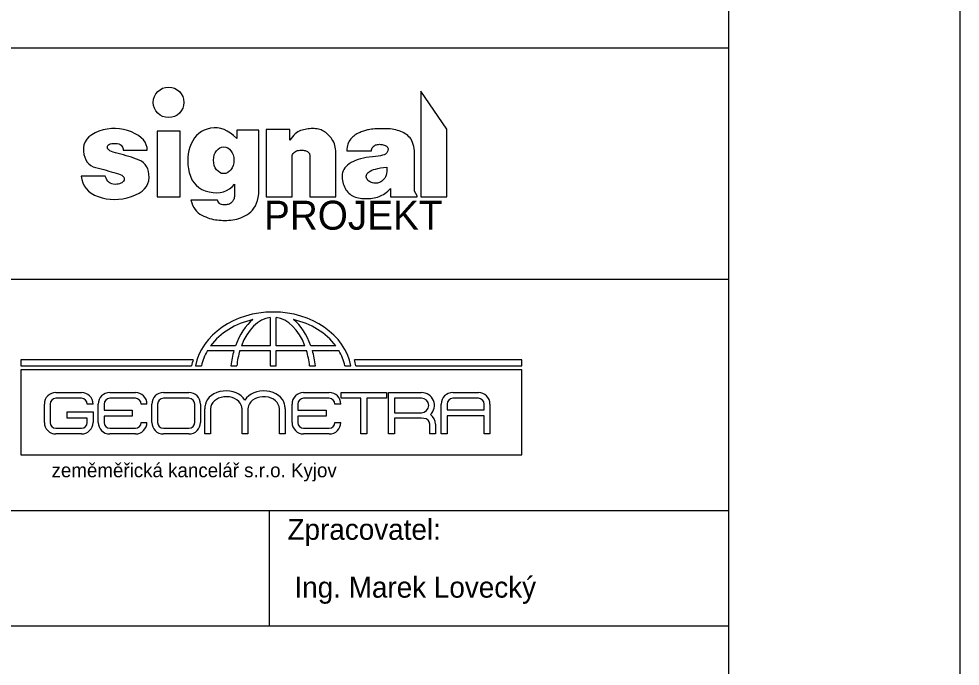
# Model space of a CAD drawing. Extents: x 1983 to 3683, y -6209 to -5764.
# Drawn here: x 2856.3 to 2937.6, y -6109.7 to -6053.7 of the extents above; entities that cross this region are included whole.
import ezdxf

# ---------------------------------------------------------------- set-up
doc = ezdxf.new("R2010")
doc.units = 0
for name, color, linetype in [('Default', 7, 'Continuous'), ('Komunikace', 7, 'Continuous'), ('Svazek obcí-chráničky', 7, 'Continuous'), ('Vrstva 19', 7, 'Continuous'), ('Vrstva 51', 7, 'Continuous')]:
    doc.layers.add(name, color=color, linetype=linetype)

msp = doc.modelspace()

# ---------------------------------------------------------------- linework, layer by layer
at = {"layer": 'Default'}
msp.add_lwpolyline([(2727.602, -6208.226), (2937.602, -6208.226), (2937.602, -5911.226), (2727.602, -5911.226)], close=True, dxfattribs=at)
at = {"layer": 'Komunikace'}
for points in [[(2893.266, -6069.106), (2893.266, -6063.266), (2891.026, -6059.986), (2891.026, -6069.106), (2893.266, -6069.106)], [(2864.538, -6069.341), (2864.9, -6069.324), (2865.266, -6069.276), (2865.637, -6069.197), (2866.013, -6069.087), (2866.368, -6068.951), (2866.676, -6068.795), (2866.937, -6068.619), (2867.151, -6068.423), (2867.318, -6068.207), (2867.439, -6067.971), (2867.512, -6067.715), (2867.539, -6067.439), (2867.528, -6067.165), (2867.49, -6066.917), (2867.424, -6066.693), (2867.33, -6066.493), (2867.209, -6066.318), (2867.059, -6066.168), (2866.882, -6066.043), (2866.678, -6065.942), (2866.458, -6065.856), (2866.236, -6065.774), (2866.012, -6065.697), (2865.786, -6065.624), (2865.557, -6065.555), (2865.326, -6065.491), (2865.092, -6065.432), (2864.857, -6065.376), (2864.635, -6065.321), (2864.444, -6065.262), (2864.283, -6065.199), (2864.153, -6065.132), (2864.053, -6065.061), (2863.983, -6064.986), (2863.944, -6064.907), (2863.936, -6064.824), (2863.952, -6064.744), (2863.989, -6064.675), (2864.045, -6064.617), (2864.121, -6064.57), (2864.217, -6064.534), (2864.332, -6064.508), (2864.468, -6064.494), (2864.623, -6064.49), (2864.778, -6064.501), (2864.914, -6064.53), (2865.029, -6064.577), (2865.123, -6064.643), (2865.198, -6064.727), (2865.253, -6064.829), (2865.287, -6064.949), (2865.302, -6065.088), (2867.381, -6065.088), (2867.361, -6064.846), (2867.299, -6064.616), (2867.194, -6064.399), (2867.046, -6064.195), (2866.856, -6064.004), (2866.622, -6063.825), (2866.345, -6063.659), (2866.026, -6063.505), (2865.684, -6063.376), (2865.339, -6063.281), (2864.991, -6063.222), (2864.641, -6063.197), (2864.288, -6063.207), (2863.932, -6063.251), (2863.574, -6063.331), (2863.213, -6063.446), (2862.875, -6063.588), (2862.586, -6063.751), (2862.345, -6063.934), (2862.153, -6064.138), (2862.009, -6064.362), (2861.915, -6064.607), (2861.868, -6064.873), (2861.871, -6065.159), (2861.91, -6065.44), (2861.976, -6065.692), (2862.069, -6065.914), (2862.187, -6066.107), (2862.332, -6066.271), (2862.503, -6066.404), (2862.7, -6066.509), (2862.923, -6066.584), (2863.158, -6066.643), (2863.389, -6066.703), (2863.617, -6066.762), (2863.841, -6066.821), (2864.061, -6066.88), (2864.278, -6066.938), (2864.491, -6066.996), (2864.701, -6067.054), (2864.893, -6067.114), (2865.054, -6067.178), (2865.185, -6067.247), (2865.284, -6067.321), (2865.353, -6067.399), (2865.391, -6067.481), (2865.398, -6067.568), (2865.374, -6067.659), (2865.327, -6067.747), (2865.266, -6067.824), (2865.191, -6067.888), (2865.101, -6067.941), (2864.997, -6067.983), (2864.878, -6068.013), (2864.745, -6068.031), (2864.598, -6068.038), (2864.45, -6068.027), (2864.314, -6067.994), (2864.19, -6067.939), (2864.079, -6067.86), (2863.98, -6067.759), (2863.894, -6067.635), (2863.82, -6067.489), (2863.758, -6067.32), (2861.678, -6067.32), (2861.722, -6067.627), (2861.805, -6067.909), (2861.928, -6068.167), (2862.091, -6068.401), (2862.293, -6068.61), (2862.535, -6068.795), (2862.816, -6068.956), (2863.137, -6069.093), (2863.48, -6069.202), (2863.828, -6069.279), (2864.181, -6069.326), (2864.538, -6069.341)], [(2870.226, -6069.106), (2870.226, -6063.426), (2868.226, -6063.426), (2868.226, -6069.106), (2870.226, -6069.106)], [(2874.086, -6071.148), (2874.254, -6071.144), (2874.424, -6071.136), (2874.596, -6071.122), (2874.77, -6071.104), (2874.944, -6071.077), (2875.118, -6071.038), (2875.292, -6070.987), (2875.465, -6070.924), (2875.638, -6070.848), (2875.811, -6070.76), (2875.984, -6070.661), (2876.156, -6070.549), (2876.32, -6070.419), (2876.469, -6070.266), (2876.601, -6070.091), (2876.718, -6069.892), (2876.819, -6069.67), (2876.904, -6069.425), (2876.973, -6069.157), (2877.026, -6068.866), (2877.026, -6063.346), (2875.106, -6063.346), (2875.106, -6064.066), (2874.84, -6063.811), (2874.57, -6063.598), (2874.295, -6063.426), (2874.016, -6063.295), (2873.733, -6063.205), (2873.446, -6063.156), (2873.154, -6063.149), (2872.858, -6063.182), (2872.571, -6063.25), (2872.306, -6063.347), (2872.062, -6063.472), (2871.84, -6063.626), (2871.64, -6063.809), (2871.462, -6064.02), (2871.306, -6064.259), (2871.171, -6064.527), (2871.06, -6064.813), (2870.975, -6065.106), (2870.916, -6065.406), (2870.883, -6065.713), (2870.876, -6066.028), (2870.895, -6066.35), (2870.94, -6066.678), (2871.011, -6067.015), (2871.111, -6067.338), (2871.243, -6067.629), (2871.409, -6067.887), (2871.607, -6068.112), (2871.838, -6068.305), (2872.101, -6068.465), (2872.397, -6068.592), (2872.726, -6068.687), (2873.062, -6068.745), (2873.381, -6068.762), (2873.681, -6068.739), (2873.964, -6068.675), (2874.229, -6068.57), (2874.477, -6068.425), (2874.707, -6068.238), (2874.918, -6068.012), (2874.918, -6069.088), (2874.9, -6069.176), (2874.877, -6069.257), (2874.849, -6069.333), (2874.817, -6069.404), (2874.781, -6069.468), (2874.74, -6069.527), (2874.694, -6069.58), (2874.644, -6069.627), (2874.588, -6069.669), (2874.526, -6069.705), (2874.456, -6069.736), (2874.379, -6069.762), (2874.295, -6069.782), (2874.204, -6069.796), (2874.106, -6069.806), (2874.001, -6069.81), (2873.897, -6069.804), (2873.804, -6069.786), (2873.72, -6069.754), (2873.647, -6069.709), (2873.584, -6069.651), (2873.532, -6069.579), (2873.489, -6069.494), (2873.457, -6069.396), (2871.15, -6069.396), (2871.219, -6069.624), (2871.302, -6069.832), (2871.399, -6070.023), (2871.51, -6070.194), (2871.635, -6070.347), (2871.773, -6070.481), (2871.926, -6070.596), (2872.092, -6070.692), (2872.264, -6070.775), (2872.435, -6070.849), (2872.604, -6070.915), (2872.772, -6070.972), (2872.938, -6071.02), (2873.103, -6071.06), (2873.266, -6071.091), (2873.428, -6071.114), (2873.59, -6071.13), (2873.753, -6071.141), (2873.919, -6071.147), (2874.086, -6071.148)], [(2883.666, -6069.106), (2883.666, -6065.306), (2883.663, -6065.136), (2883.649, -6064.973), (2883.624, -6064.816), (2883.589, -6064.666), (2883.543, -6064.522), (2883.486, -6064.385), (2883.418, -6064.255), (2883.339, -6064.131), (2883.254, -6064.015), (2883.167, -6063.907), (2883.078, -6063.807), (2882.987, -6063.716), (2882.894, -6063.632), (2882.799, -6063.557), (2882.702, -6063.49), (2882.603, -6063.431), (2882.501, -6063.38), (2882.395, -6063.335), (2882.284, -6063.298), (2882.169, -6063.268), (2882.049, -6063.244), (2881.926, -6063.227), (2881.798, -6063.218), (2881.666, -6063.215), (2881.532, -6063.218), (2881.399, -6063.226), (2881.268, -6063.239), (2881.138, -6063.257), (2881.009, -6063.28), (2880.881, -6063.308), (2880.754, -6063.341), (2880.629, -6063.378), (2880.505, -6063.427), (2880.384, -6063.492), (2880.265, -6063.573), (2880.149, -6063.671), (2880.034, -6063.785), (2879.923, -6063.915), (2879.813, -6064.062), (2879.706, -6064.226), (2879.706, -6063.306), (2877.666, -6063.306), (2877.666, -6069.106), (2879.906, -6069.106), (2879.906, -6065.546), (2879.941, -6065.455), (2879.985, -6065.374), (2880.039, -6065.303), (2880.104, -6065.242), (2880.178, -6065.191), (2880.262, -6065.15), (2880.356, -6065.119), (2880.46, -6065.098), (2880.566, -6065.085), (2880.666, -6065.078), (2880.762, -6065.077), (2880.852, -6065.082), (2880.937, -6065.094), (2881.017, -6065.111), (2881.091, -6065.135), (2881.16, -6065.165), (2881.223, -6065.199), (2881.277, -6065.238), (2881.322, -6065.28), (2881.36, -6065.326), (2881.389, -6065.375), (2881.41, -6065.428), (2881.422, -6065.485), (2881.426, -6065.546), (2881.426, -6069.106), (2883.666, -6069.106)], [(2886.229, -6069.27), (2886.391, -6069.267), (2886.548, -6069.258), (2886.702, -6069.244), (2886.851, -6069.224), (2886.995, -6069.198), (2887.135, -6069.166), (2887.271, -6069.129), (2887.403, -6069.086), (2887.532, -6069.035), (2887.659, -6068.973), (2887.784, -6068.901), (2887.908, -6068.819), (2888.03, -6068.726), (2888.15, -6068.623), (2888.269, -6068.51), (2888.386, -6068.386), (2888.386, -6069.106), (2890.706, -6069.106), (2890.706, -6069.026), (2890.466, -6068.626), (2890.466, -6065.146), (2890.44, -6064.941), (2890.404, -6064.751), (2890.359, -6064.575), (2890.304, -6064.414), (2890.239, -6064.267), (2890.165, -6064.135), (2890.082, -6064.017), (2889.989, -6063.914), (2889.888, -6063.821), (2889.78, -6063.735), (2889.667, -6063.656), (2889.547, -6063.585), (2889.421, -6063.52), (2889.288, -6063.461), (2889.15, -6063.41), (2889.005, -6063.366), (2888.853, -6063.328), (2888.694, -6063.296), (2888.527, -6063.27), (2888.354, -6063.249), (2888.173, -6063.234), (2887.985, -6063.225), (2887.79, -6063.221), (2887.588, -6063.223), (2887.389, -6063.229), (2887.205, -6063.237), (2887.036, -6063.248), (2886.881, -6063.261), (2886.741, -6063.276), (2886.616, -6063.293), (2886.506, -6063.312), (2886.41, -6063.334), (2886.322, -6063.358), (2886.232, -6063.383), (2886.142, -6063.411), (2886.051, -6063.44), (2885.96, -6063.472), (2885.868, -6063.505), (2885.775, -6063.541), (2885.682, -6063.578), (2885.589, -6063.62), (2885.496, -6063.668), (2885.405, -6063.724), (2885.315, -6063.786), (2885.226, -6063.855), (2885.138, -6063.931), (2885.05, -6064.013), (2884.964, -6064.103), (2884.884, -6064.2), (2884.815, -6064.307), (2884.756, -6064.424), (2884.709, -6064.549), (2884.672, -6064.684), (2884.646, -6064.829), (2884.631, -6064.983), (2884.626, -6065.146), (2886.746, -6065.146), (2886.762, -6065.049), (2886.786, -6064.962), (2886.819, -6064.884), (2886.86, -6064.815), (2886.91, -6064.756), (2886.969, -6064.705), (2887.036, -6064.664), (2887.112, -6064.631), (2887.193, -6064.607), (2887.274, -6064.589), (2887.355, -6064.578), (2887.437, -6064.573), (2887.52, -6064.575), (2887.603, -6064.583), (2887.687, -6064.598), (2887.771, -6064.619), (2887.851, -6064.645), (2887.923, -6064.672), (2887.985, -6064.702), (2888.039, -6064.734), (2888.084, -6064.769), (2888.121, -6064.805), (2888.148, -6064.843), (2888.167, -6064.884), (2888.178, -6064.927), (2888.183, -6064.973), (2888.182, -6065.021), (2888.175, -6065.073), (2888.161, -6065.127), (2888.141, -6065.184), (2888.115, -6065.243), (2888.082, -6065.306), (2888.032, -6065.367), (2887.951, -6065.423), (2887.839, -6065.474), (2887.698, -6065.519), (2887.526, -6065.559), (2887.323, -6065.594), (2887.091, -6065.624), (2886.828, -6065.648), (2886.556, -6065.674), (2886.296, -6065.712), (2886.049, -6065.76), (2885.814, -6065.818), (2885.591, -6065.887), (2885.381, -6065.967), (2885.183, -6066.057), (2884.997, -6066.157), (2884.828, -6066.265), (2884.679, -6066.378), (2884.552, -6066.495), (2884.445, -6066.617), (2884.36, -6066.743), (2884.295, -6066.874), (2884.251, -6067.009), (2884.228, -6067.149), (2884.22, -6067.29), (2884.221, -6067.43), (2884.231, -6067.569), (2884.25, -6067.707), (2884.278, -6067.844), (2884.315, -6067.979), (2884.361, -6068.114), (2884.416, -6068.247), (2884.479, -6068.375), (2884.549, -6068.494), (2884.626, -6068.605), (2884.709, -6068.706), (2884.8, -6068.799), (2884.898, -6068.883), (2885.002, -6068.957), (2885.114, -6069.023), (2885.232, -6069.081), (2885.356, -6069.131), (2885.486, -6069.174), (2885.622, -6069.208), (2885.765, -6069.235), (2885.913, -6069.254), (2886.068, -6069.266), (2886.229, -6069.27)], [(2886.945, -6067.925), (2886.842, -6067.905), (2886.747, -6067.877), (2886.66, -6067.841), (2886.581, -6067.797), (2886.511, -6067.746), (2886.448, -6067.687), (2886.393, -6067.62), (2886.346, -6067.545), (2886.312, -6067.468), (2886.294, -6067.391), (2886.293, -6067.315), (2886.308, -6067.24), (2886.341, -6067.165), (2886.39, -6067.092), (2886.456, -6067.02), (2886.538, -6066.948), (2886.642, -6066.88), (2886.77, -6066.817), (2886.924, -6066.759), (2887.103, -6066.707), (2887.307, -6066.66), (2887.537, -6066.618), (2887.791, -6066.581), (2888.071, -6066.55), (2888.075, -6066.748), (2888.067, -6066.931), (2888.045, -6067.097), (2888.01, -6067.246), (2887.963, -6067.38), (2887.902, -6067.497), (2887.829, -6067.599), (2887.743, -6067.684), (2887.649, -6067.755), (2887.554, -6067.814), (2887.457, -6067.862), (2887.358, -6067.898), (2887.257, -6067.923), (2887.155, -6067.935), (2887.051, -6067.936), (2886.945, -6067.925)]]:
    msp.add_lwpolyline(points, dxfattribs=at)
msp.add_circle((2869.226, -6060.946), 1.32, dxfattribs=at)
msp.add_ellipse((2873.986, -6065.946), major_axis=(0, 1.16), ratio=0.758621, dxfattribs=at)
at = {"layer": 'Svazek obcí-chráničky'}
for p, q in [((2877.997, -6079.539), (2877.997, -6081.985)), ((2878.504, -6081.985), (2878.504, -6079.537)), ((2875.003, -6081.985), (2872.858, -6081.985)), ((2877.997, -6081.985), (2875.52, -6081.985)), ((2880.998, -6081.985), (2878.504, -6081.985)), ((2883.66, -6081.985), (2881.515, -6081.985)), ((2872.583, -6082.397), (2874.871, -6082.397)), ((2875.381, -6082.397), (2877.997, -6082.397)), ((2877.997, -6082.397), (2877.997, -6083.717)), ((2878.504, -6083.717), (2878.504, -6082.397)), ((2878.504, -6082.397), (2881.138, -6082.397)), ((2881.648, -6082.397), (2883.935, -6082.397)), ((2871.352, -6083.186), (2856.472, -6083.186)), ((2856.472, -6083.186), (2856.472, -6083.717)), ((2856.472, -6083.717), (2871.215, -6083.717)), ((2871.54, -6083.717), (2872.057, -6083.717)), ((2874.614, -6083.717), (2875.114, -6083.717)), ((2877.997, -6083.717), (2878.504, -6083.717)), ((2881.405, -6083.717), (2881.905, -6083.717)), ((2884.461, -6083.717), (2884.978, -6083.717)), ((2899.75, -6083.186), (2885.272, -6083.186)), ((2885.41, -6083.717), (2899.75, -6083.717)), ((2899.75, -6083.717), (2899.75, -6083.186)), ((2899.749, -6084.061), (2856.466, -6084.061)), ((2856.466, -6084.061), (2856.466, -6091.399)), ((2899.749, -6091.399), (2899.749, -6084.061)), ((2859.491, -6086.027), (2861.701, -6086.027)), ((2864.147, -6086.027), (2866.358, -6086.027)), ((2868.771, -6086.027), (2870.981, -6086.027)), ((2880.889, -6086.027), (2883.1, -6086.027)), ((2888.227, -6086.027), (2891.071, -6086.027)), ((2893.775, -6086.027), (2895.986, -6086.027)), ((2858.493, -6088.611), (2858.493, -6087.025)), ((2858.992, -6087.025), (2858.992, -6088.611)), ((2861.701, -6086.526), (2859.491, -6086.526)), ((2862.699, -6087.025), (2862.2, -6087.025)), ((2863.149, -6088.611), (2863.149, -6087.025)), ((2863.648, -6087.025), (2863.648, -6087.536)), ((2866.358, -6086.526), (2864.147, -6086.526)), ((2867.355, -6087.025), (2866.857, -6087.025)), ((2867.773, -6088.611), (2867.773, -6087.025)), ((2868.272, -6087.025), (2868.272, -6088.611)), ((2870.981, -6086.526), (2868.771, -6086.526)), ((2871.481, -6088.611), (2871.481, -6087.025)), ((2871.979, -6087.025), (2871.979, -6088.611)), ((2879.892, -6088.611), (2879.892, -6087.025)), ((2880.39, -6087.025), (2880.39, -6087.536)), ((2883.1, -6086.526), (2880.889, -6086.526)), ((2884.098, -6087.025), (2883.599, -6087.025)), ((2885.832, -6089.609), (2885.832, -6086.514)), ((2886.336, -6086.514), (2886.336, -6089.609)), ((2891.071, -6086.516), (2888.731, -6086.516)), ((2888.731, -6086.516), (2888.731, -6087.766)), ((2892.777, -6089.609), (2892.777, -6087.025)), ((2893.276, -6087.025), (2893.276, -6087.534)), ((2895.986, -6086.526), (2893.775, -6086.526)), ((2896.485, -6087.534), (2896.485, -6087.025)), ((2896.983, -6087.025), (2896.983, -6089.609)), ((2860.466, -6088.233), (2860.466, -6087.689)), ((2860.466, -6087.689), (2862.699, -6087.689)), ((2862.699, -6087.689), (2862.699, -6088.611)), ((2863.648, -6087.536), (2866.091, -6087.536)), ((2866.091, -6087.536), (2866.091, -6088.08)), ((2872.352, -6089.609), (2872.352, -6087.424)), ((2872.852, -6087.424), (2872.852, -6089.609)), ((2875.572, -6089.609), (2875.572, -6087.424)), ((2876.072, -6087.424), (2876.072, -6089.609)), ((2878.791, -6089.609), (2878.791, -6087.424)), ((2879.291, -6087.424), (2879.291, -6089.609)), ((2880.39, -6087.536), (2882.833, -6087.536)), ((2882.833, -6087.536), (2882.833, -6088.08)), ((2888.731, -6087.766), (2891.071, -6087.766)), ((2893.276, -6087.534), (2896.485, -6087.534)), ((2862.2, -6088.233), (2860.466, -6088.233)), ((2862.2, -6088.611), (2862.2, -6088.233)), ((2866.091, -6088.08), (2863.648, -6088.08)), ((2863.648, -6088.08), (2863.648, -6088.611)), ((2866.857, -6088.611), (2867.355, -6088.611)), ((2882.833, -6088.08), (2880.39, -6088.08)), ((2880.39, -6088.08), (2880.39, -6088.611)), ((2883.599, -6088.611), (2884.098, -6088.611)), ((2891.071, -6088.255), (2888.731, -6088.255)), ((2891.285, -6088.259), (2891.071, -6088.255)), ((2896.485, -6088.037), (2893.276, -6088.037)), ((2893.276, -6088.037), (2893.276, -6089.609)), ((2896.485, -6089.609), (2896.485, -6088.037)), ((2859.491, -6089.11), (2861.701, -6089.11)), ((2864.147, -6089.11), (2866.358, -6089.11)), ((2868.771, -6089.11), (2870.981, -6089.11)), ((2880.889, -6089.11), (2883.1, -6089.11)), ((2891.784, -6089.609), (2891.784, -6088.758)), ((2892.283, -6088.758), (2892.283, -6089.609)), ((2861.701, -6089.609), (2859.491, -6089.609)), ((2866.358, -6089.609), (2864.147, -6089.609)), ((2870.981, -6089.609), (2868.771, -6089.609)), ((2872.852, -6089.609), (2872.352, -6089.609)), ((2876.072, -6089.609), (2875.572, -6089.609)), ((2879.291, -6089.609), (2878.791, -6089.609)), ((2883.1, -6089.609), (2880.889, -6089.609)), ((2886.336, -6089.609), (2885.832, -6089.609)), ((2892.283, -6089.609), (2891.784, -6089.609)), ((2893.276, -6089.609), (2892.777, -6089.609)), ((2896.983, -6089.609), (2896.485, -6089.609)), ((2856.466, -6091.399), (2899.749, -6091.399))]:
    msp.add_line(p, q, dxfattribs=at)
for points in [[(2885.832, -6086.514), (2884.134, -6086.514), (2884.134, -6086.027), (2888.048, -6086.027)], [(2888.048, -6086.027), (2888.048, -6086.514), (2886.336, -6086.514)], [(2888.731, -6088.255), (2888.731, -6089.609), (2888.227, -6089.609), (2888.227, -6086.027)]]:
    msp.add_lwpolyline(points, dxfattribs=at)
for centre, radius, start, end in [((2859.491, -6087.025), 0.998, 90, 180), ((2861.701, -6087.025), 0.998, 360, 90), ((2864.147, -6087.025), 0.998, 90, 180), ((2866.358, -6087.025), 0.998, 360, 90), ((2868.771, -6087.025), 0.998, 90, 180), ((2870.981, -6087.025), 0.998, 360, 90), ((2880.889, -6087.025), 0.998, 90, 180), ((2883.1, -6087.025), 0.998, 360, 90), ((2891.071, -6087.141), 1.114, 314.45734, 90), ((2893.775, -6087.025), 0.998, 90, 180), ((2895.986, -6087.025), 0.998, 360, 90), ((2859.491, -6087.025), 0.499, 90, 180), ((2861.701, -6087.025), 0.499, 0, 90), ((2864.147, -6087.025), 0.499, 90, 180), ((2866.358, -6087.025), 0.499, 0, 90), ((2868.771, -6087.025), 0.499, 90, 180), ((2870.981, -6087.025), 0.499, 0, 90), ((2874.289, -6087.474), 1.938, 166.96576, 178.52091), ((2877.354, -6087.474), 1.938, 1.47909, 13.03424), ((2880.889, -6087.025), 0.499, 90, 180), ((2883.1, -6087.025), 0.499, 0, 90), ((2891.071, -6087.141), 0.625, 270, 90), ((2893.775, -6087.025), 0.499, 90, 180), ((2895.986, -6087.025), 0.499, 0, 90), ((2874.617, -6087.489), 0.957, 3.86486, 22.41569), ((2877.305, -6087.546), 1.238, 162.61388, 174.3506), ((2859.491, -6088.611), 0.998, 180, 270), ((2859.491, -6088.611), 0.499, 180, 270), ((2861.701, -6088.611), 0.998, 270, 0), ((2861.701, -6088.611), 0.499, 270, 0), ((2864.147, -6088.611), 0.998, 180, 270), ((2864.147, -6088.611), 0.499, 180, 270), ((2866.358, -6088.611), 0.998, 270, 0), ((2866.358, -6088.611), 0.499, 270, 0), ((2868.771, -6088.611), 0.998, 180, 270), ((2868.771, -6088.611), 0.499, 180, 270), ((2870.981, -6088.611), 0.998, 270, 0), ((2870.981, -6088.611), 0.499, 270, 0), ((2880.889, -6088.611), 0.998, 180, 270), ((2880.889, -6088.611), 0.499, 180, 270), ((2883.1, -6088.611), 0.998, 270, 0), ((2883.1, -6088.611), 0.499, 270, 0), ((2891.285, -6088.758), 0.499, 0, 90), ((2891.285, -6088.758), 0.998, 360, 55.44734)]:
    msp.add_arc(centre, radius, start, end, dxfattribs=at)
for centre, major_axis, ratio, start_param, end_param in [((2878.259, -6084.589), (-6.804, 0), 0.811768, 3.300239, 6.124539), ((2878.259, -6084.589), (-6.296, 0), 0.804826, 4.992897, 5.743383), ((2878.259, -6084.589), (0, 5.524), 0.668443, 0.491666, 1.079789), ((2878.259, -6084.589), (0, 5.067), 0.630136, 0.08224, 1.030995), ((2878.259, -6084.589), (0, 5.067), 0.630136, 5.252191, 6.206521), ((2878.259, -6084.589), (0, 5.524), 0.668443, 5.203397, 5.79152), ((2878.259, -6084.589), (-6.296, 0), 0.804826, 3.681394, 4.431881), ((2878.259, -6084.589), (-6.296, 0), 0.804826, 5.835664, 6.110118), ((2878.259, -6084.589), (0, 5.524), 0.668443, 1.16256, 1.41215), ((2878.259, -6084.589), (0, 5.067), 0.630136, 1.123275, 1.397729), ((2878.259, -6084.589), (0, 5.067), 0.630136, 4.885456, 5.159911), ((2878.259, -6084.589), (0, 5.524), 0.668443, 4.871035, 5.120625), ((2878.259, -6084.589), (-6.296, 0), 0.804826, 3.31466, 3.589114), ((2877.933, -6084.589), (-6.804, 0), 0.811768, 6.026233, 6.124539), ((2878.691, -6084.589), (-6.804, 0), 0.811768, 3.300239, 3.398545), ((2874.181, -6087.269), (1.805, 0), 0.766187, 0.429647, 2.97338), ((2877.462, -6087.269), (-1.805, 0), 0.766187, 3.309805, 5.853538), ((2874.206, -6087.424), (1.354, 0), 0.766187, 0.29376, 3.141593), ((2877.437, -6087.424), (-1.354, 0), 0.766187, 3.141593, 6.041607)]:
    msp.add_ellipse(centre, major_axis=major_axis, ratio=ratio, start_param=start_param, end_param=end_param, dxfattribs=at)
at = {"layer": 'Vrstva 19'}
msp.add_lwpolyline([(2747.602, -5931.226), (2917.602, -5931.226), (2917.602, -6191.226), (2747.602, -6191.226)], close=True, dxfattribs=at)
at = {"layer": 'Vrstva 51'}
for p, q in [((2747.602, -6076.226), (2917.602, -6076.226)), ((2747.602, -6096.226), (2917.602, -6096.226)), ((2877.952, -6106.226), (2877.952, -6096.226))]:
    msp.add_line(p, q, dxfattribs=at)
msp.add_lwpolyline([(2747.602, -6056.226), (2917.602, -6056.226), (2917.602, -6106.226), (2747.602, -6106.226)], close=True, dxfattribs=at)

# ---------------------------------------------------------------- texts
at = {"layer": 'Komunikace'}
msp.add_text('PROJEKT', height=2.5, dxfattribs=at).set_placement((2877.467, -6071.949))
at = {"layer": 'Svazek obcí-chráničky'}
msp.add_text('zeměměřická kancelář s.r.o. Kyjov', height=1.20984, dxfattribs=at).set_placement((2859.117, -6093.348))
at = {"layer": 'Vrstva 51'}
for s, p in [('Zpracovatel:', (2879.498, -6098.753)), ('Ing. Marek Lovecký', (2880.099, -6103.753))]:
    msp.add_text(s, height=1.8, dxfattribs=at).set_placement(p)

doc.saveas('drawing.dxf')
